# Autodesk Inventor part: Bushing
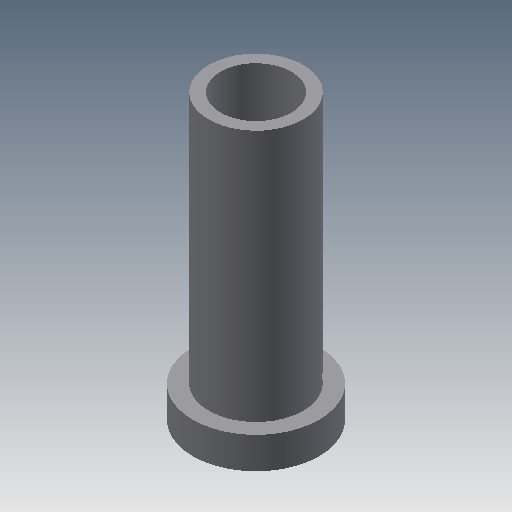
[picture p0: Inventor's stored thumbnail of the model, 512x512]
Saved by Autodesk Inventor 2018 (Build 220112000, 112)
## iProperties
Shininess: 77.0
Length Units: 11269
Angle Units: 11279
Time Units: 11290
Mass Units: 11283
Length Display Precision: 3
Angle Display Precision: 2
Created: 2002-02
Part Number: Bushing
Document SubType Name: Modeling
Designer: ***
Density: 1 g/cm^3
Material: Generic
Appearance: Default
Density: 0.0
Volumn: 0.0
Area: 0.0
PropertySet Name: Model Information
Control State: 0
Master: False
Checked Out: False
Author: ***
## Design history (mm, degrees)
sketch "Sketch1"
  geometry: L1 (6.25, 50.44)-(6.25, 5.44); L2 (6.25, 5.44)-(10.625, 5.44); L3 (10.625, 5.44)-(10.625, 10.44); L4 (10.625, 10.44)-(8.125, 10.44); L5 (8.125, 10.44)-(8.125, 50.44); L6 (8.125, 50.44)-(6.25, 50.44); L7 (0.625, 34.884)-(0.625, 0)
  constraints: 14 end point, 4 parallel, 2 perpendicular, 1 vertical
  dimensions: "d0" = 20 diameter of L3 L7; "d1" = 11.25 diameter of L1 L7; "d2" = 15 diameter of L5 L7; "d4" = 5 distance of L2.end L3.end; "d5" = 45 distance of L1.start L1.end
revolve "Revolution1" sketch "Sketch1" stored, may be unused: angle "d3" = 90 deg
body "Solid1"
